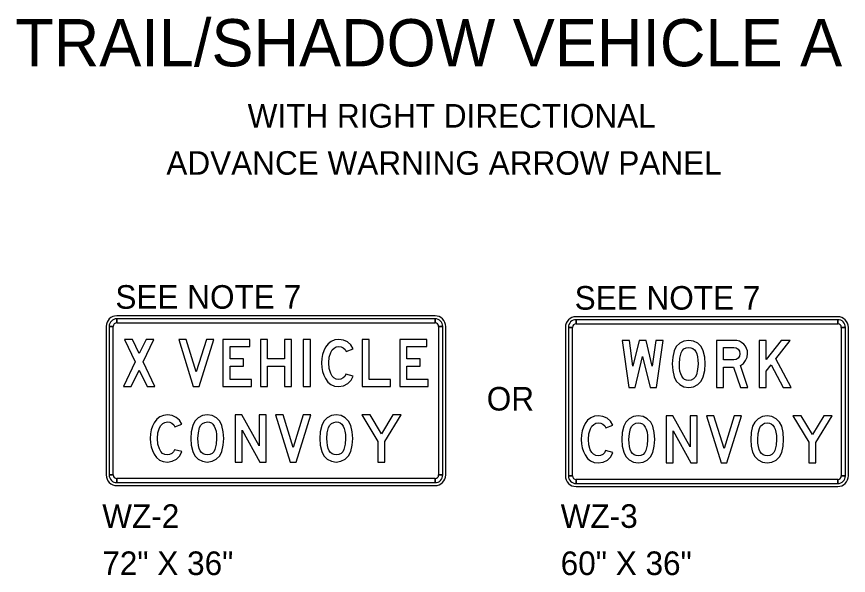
# Model space of a CAD drawing. Extents: x 1806907 to 1812607, y 675071 to 676228.
# Drawn here: x 1811769.5 to 1811981.1, y 675736.2 to 675878.3 of the extents above; entities that cross this region are included whole.
import ezdxf

# ---------------------------------------------------------------- set-up
doc = ezdxf.new("R2010")
doc.units = 0
doc.layers.add('Working Level 1', color=7, linetype='Continuous')

msp = doc.modelspace()

# ---------------------------------------------------------------- linework, layer by layer
at = {"layer": 'Working Level 1'}
for p, q in [((1811875.95, 675802.2), (1811794.95, 675802.2)), ((1811794.95, 675800.4), (1811794.95, 675801.45)), ((1811875.95, 675801.45), (1811875.95, 675800.4)), ((1811978.42, 675801.97), (1811911.82, 675801.97)), ((1811911.82, 675800.17), (1811911.82, 675801.22)), ((1811978.42, 675801.22), (1811978.42, 675800.17)), ((1811792.25, 675799.5), (1811792.25, 675761.7)), ((1811793, 675799.5), (1811794.05, 675799.5)), ((1811876.85, 675799.5), (1811877.9, 675799.5)), ((1811878.65, 675761.7), (1811878.65, 675799.5)), ((1811909.12, 675799.27), (1811909.12, 675761.47)), ((1811909.87, 675799.27), (1811910.92, 675799.27)), ((1811979.32, 675799.27), (1811980.37, 675799.27)), ((1811981.12, 675761.47), (1811981.12, 675799.27)), ((1811794.05, 675761.7), (1811793, 675761.7)), ((1811794.95, 675759.75), (1811794.95, 675760.8)), ((1811875.95, 675760.8), (1811875.95, 675759.75)), ((1811877.9, 675761.7), (1811876.85, 675761.7)), ((1811910.92, 675761.47), (1811909.87, 675761.47)), ((1811911.82, 675759.52), (1811911.82, 675760.57)), ((1811978.42, 675760.57), (1811978.42, 675759.52)), ((1811980.37, 675761.47), (1811979.32, 675761.47)), ((1811794.95, 675759), (1811875.95, 675759)), ((1811911.82, 675758.77), (1811978.42, 675758.77))]:
    msp.add_line(p, q, dxfattribs=at)
for points in [[(1811875.95, 675801.45), (1811794.95, 675801.45), (1811794.95, 675800.4), (1811875.95, 675800.4), (1811875.95, 675801.45)], [(1811978.42, 675801.22), (1811911.82, 675801.22), (1811911.82, 675800.17), (1811978.42, 675800.17), (1811978.42, 675801.22)], [(1811793, 675799.5), (1811793, 675761.7), (1811794.05, 675761.7), (1811794.05, 675799.5), (1811793, 675799.5)], [(1811877.9, 675761.7), (1811877.9, 675799.5), (1811876.85, 675799.5), (1811876.85, 675761.7), (1811877.9, 675761.7)], [(1811909.87, 675799.27), (1811909.87, 675761.47), (1811910.92, 675761.47), (1811910.92, 675799.27), (1811909.87, 675799.27)], [(1811980.37, 675761.47), (1811980.37, 675799.27), (1811979.32, 675799.27), (1811979.32, 675761.47), (1811980.37, 675761.47)], [(1811804.65, 675784.2), (1811801.66, 675790.48), (1811804.4, 675796.2), (1811802.39, 675796.2), (1811800.65, 675792.58), (1811798.93, 675796.2), (1811796.92, 675796.2), (1811799.65, 675790.47), (1811796.64, 675784.2), (1811798.64, 675784.2), (1811800.65, 675788.37), (1811802.64, 675784.2)], [(1811819.64, 675796.2), (1811817.74, 675796.2), (1811815.16, 675787.91), (1811812.59, 675796.2), (1811810.7, 675796.2), (1811814.42, 675784.2), (1811815.91, 675784.2)], [(1811829.2, 675786.01), (1811823.76, 675786.01), (1811823.76, 675789.41), (1811827.16, 675789.41), (1811827.16, 675791.22), (1811823.76, 675791.22), (1811823.76, 675794.39), (1811828.84, 675794.39), (1811828.84, 675796.2), (1811821.95, 675796.2), (1811821.95, 675784.2), (1811829.2, 675784.2)], [(1811839.43, 675784.2), (1811839.43, 675796.2), (1811837.62, 675796.2), (1811837.62, 675791.22), (1811833.32, 675791.22), (1811833.32, 675796.2), (1811831.51, 675796.2), (1811831.51, 675784.2), (1811833.32, 675784.2), (1811833.32, 675789.41), (1811837.62, 675789.41), (1811837.62, 675784.2)], [(1811844.2, 675784.2), (1811844.2, 675796.2), (1811842.39, 675796.2), (1811842.39, 675784.2)], [(1811855.08, 675786.86), (1811853.27, 675787.32), (1811853, 675786.8), (1811852.56, 675786.38), (1811852, 675786.1), (1811851.37, 675786.01), (1811850.74, 675786.11), (1811850.2, 675786.39), (1811849.75, 675786.87), (1811849.38, 675787.54), (1811849.01, 675788.77), (1811848.89, 675790.2), (1811849.01, 675791.64), (1811849.39, 675792.87), (1811849.77, 675793.53), (1811850.24, 675794.01), (1811850.79, 675794.29), (1811851.43, 675794.39), (1811852.03, 675794.3), (1811852.58, 675794.06), (1811853.03, 675793.66), (1811853.34, 675793.16), (1811855.08, 675793.84), (1811854.5, 675794.81), (1811853.64, 675795.56), (1811852.6, 675796.04), (1811851.46, 675796.2), (1811850.4, 675796.07), (1811849.48, 675795.7), (1811848.7, 675795.07), (1811848.04, 675794.2), (1811847.62, 675793.33), (1811847.32, 675792.38), (1811847.14, 675791.34), (1811847.08, 675790.21), (1811847.13, 675789.08), (1811847.31, 675788.04), (1811847.61, 675787.09), (1811848.03, 675786.22), (1811848.67, 675785.34), (1811849.45, 675784.71), (1811850.36, 675784.32), (1811851.4, 675784.2), (1811852.62, 675784.38), (1811853.72, 675784.94), (1811854.57, 675785.79)], [(1811864.64, 675784.2), (1811864.64, 675786.01), (1811859.2, 675786.01), (1811859.2, 675796.2), (1811857.39, 675796.2), (1811857.39, 675784.2)], [(1811874.21, 675786.01), (1811868.76, 675786.01), (1811868.76, 675789.41), (1811872.16, 675789.41), (1811872.16, 675791.22), (1811868.76, 675791.22), (1811868.76, 675794.39), (1811873.84, 675794.39), (1811873.84, 675796.2), (1811866.95, 675796.2), (1811866.95, 675784.2), (1811874.21, 675784.2)], [(1811933.98, 675795.96), (1811932.15, 675795.96), (1811931.23, 675789.39), (1811929.64, 675795.96), (1811927.89, 675795.96), (1811926.31, 675789.38), (1811925.39, 675795.96), (1811923.56, 675795.96), (1811925.24, 675783.97), (1811926.87, 675783.97), (1811928.77, 675791.86), (1811930.67, 675783.97), (1811932.3, 675783.97)], [(1811944.68, 675789.97), (1811944.56, 675791.68), (1811944.19, 675793.29), (1811943.65, 675794.37), (1811942.79, 675795.23), (1811941.71, 675795.78), (1811940.49, 675795.96), (1811939.27, 675795.78), (1811938.19, 675795.23), (1811937.33, 675794.37), (1811936.79, 675793.28), (1811936.43, 675791.67), (1811936.31, 675789.97), (1811936.43, 675788.27), (1811936.79, 675786.66), (1811937.33, 675785.58), (1811938.19, 675784.72), (1811939.27, 675784.15), (1811940.49, 675783.97), (1811941.7, 675784.15), (1811942.79, 675784.71), (1811943.64, 675785.56), (1811944.18, 675786.64), (1811944.55, 675788.25)], [(1811955.56, 675783.97), (1811953.67, 675789.57), (1811954.41, 675790.09), (1811954.98, 675790.81), (1811955.36, 675791.67), (1811955.48, 675792.59), (1811955.42, 675793.26), (1811955.23, 675793.88), (1811954.92, 675794.45), (1811954.48, 675794.97), (1811953.95, 675795.41), (1811953.38, 675795.72), (1811952.76, 675795.9), (1811952.08, 675795.96), (1811947.55, 675795.96), (1811947.55, 675783.97), (1811949.37, 675783.97), (1811949.37, 675789.17), (1811951.88, 675789.17), (1811953.65, 675783.97)], [(1811966.56, 675783.97), (1811962.66, 675791.28), (1811966.27, 675795.96), (1811963.98, 675795.96), (1811960.24, 675791.1), (1811960.24, 675795.96), (1811958.43, 675795.96), (1811958.43, 675783.97), (1811960.24, 675783.97), (1811960.24, 675788.14), (1811961.45, 675789.7), (1811964.51, 675783.97)], [(1811942.87, 675789.97), (1811942.76, 675788.51), (1811942.45, 675787.15), (1811942.16, 675786.59), (1811941.71, 675786.15), (1811941.14, 675785.87), (1811940.5, 675785.78), (1811939.94, 675785.84), (1811939.45, 675786.04), (1811939.04, 675786.36), (1811938.71, 675786.82), (1811938.45, 675787.41), (1811938.26, 675788.13), (1811938.15, 675788.98), (1811938.12, 675789.97), (1811938.22, 675791.42), (1811938.54, 675792.77), (1811938.83, 675793.33), (1811939.28, 675793.78), (1811939.85, 675794.06), (1811940.5, 675794.15), (1811941.05, 675794.09), (1811941.53, 675793.89), (1811941.94, 675793.56), (1811942.28, 675793.11), (1811942.53, 675792.52), (1811942.72, 675791.8), (1811942.83, 675790.95)], [(1811949.37, 675790.98), (1811949.37, 675794.15), (1811952.01, 675794.15), (1811952.58, 675794.03), (1811953.07, 675793.68), (1811953.4, 675793.17), (1811953.51, 675792.57), (1811953.4, 675791.96), (1811953.07, 675791.45), (1811952.58, 675791.1), (1811952.01, 675790.98)], [(1811811.49, 675767.66), (1811809.67, 675768.12), (1811809.41, 675767.6), (1811808.97, 675767.18), (1811808.4, 675766.9), (1811807.78, 675766.81), (1811807.15, 675766.91), (1811806.61, 675767.19), (1811806.15, 675767.67), (1811805.78, 675768.34), (1811805.41, 675769.57), (1811805.29, 675771), (1811805.42, 675772.44), (1811805.8, 675773.67), (1811806.18, 675774.33), (1811806.64, 675774.81), (1811807.2, 675775.09), (1811807.84, 675775.19), (1811808.44, 675775.1), (1811808.99, 675774.86), (1811809.44, 675774.46), (1811809.75, 675773.96), (1811811.49, 675774.64), (1811810.9, 675775.61), (1811810.05, 675776.36), (1811809.01, 675776.84), (1811807.87, 675777), (1811806.81, 675776.87), (1811805.89, 675776.5), (1811805.1, 675775.87), (1811804.45, 675775), (1811804.02, 675774.13), (1811803.72, 675773.18), (1811803.54, 675772.14), (1811803.48, 675771.01), (1811803.54, 675769.88), (1811803.72, 675768.84), (1811804.01, 675767.89), (1811804.44, 675767.02), (1811805.08, 675766.14), (1811805.85, 675765.51), (1811806.76, 675765.12), (1811807.81, 675765), (1811809.03, 675765.18), (1811810.12, 675765.74), (1811810.98, 675766.59)], [(1811822.17, 675771.01), (1811822.05, 675772.72), (1811821.68, 675774.32), (1811821.14, 675775.4), (1811820.28, 675776.26), (1811819.19, 675776.81), (1811817.97, 675777), (1811816.75, 675776.81), (1811815.67, 675776.26), (1811814.82, 675775.4), (1811814.28, 675774.31), (1811813.91, 675772.71), (1811813.79, 675771.01), (1811813.91, 675769.31), (1811814.28, 675767.7), (1811814.82, 675766.61), (1811815.67, 675765.75), (1811816.75, 675765.19), (1811817.97, 675765), (1811819.19, 675765.18), (1811820.27, 675765.74), (1811821.13, 675766.59), (1811821.67, 675767.68), (1811822.04, 675769.29)], [(1811832.97, 675765), (1811832.97, 675777), (1811831.16, 675777), (1811831.16, 675769.11), (1811826.78, 675777), (1811825.04, 675777), (1811825.04, 675765), (1811826.86, 675765), (1811826.86, 675773.14), (1811831.37, 675765)], [(1811844.29, 675777), (1811842.4, 675777), (1811839.82, 675768.71), (1811837.25, 675777), (1811835.36, 675777), (1811839.07, 675765), (1811840.56, 675765)], [(1811854.98, 675771.01), (1811854.86, 675772.72), (1811854.49, 675774.32), (1811853.95, 675775.4), (1811853.09, 675776.26), (1811852.01, 675776.81), (1811850.79, 675777), (1811849.57, 675776.81), (1811848.49, 675776.26), (1811847.63, 675775.4), (1811847.09, 675774.31), (1811846.73, 675772.71), (1811846.61, 675771.01), (1811846.73, 675769.31), (1811847.09, 675767.7), (1811847.63, 675766.61), (1811848.49, 675765.75), (1811849.57, 675765.19), (1811850.79, 675765), (1811852, 675765.18), (1811853.09, 675765.74), (1811853.94, 675766.59), (1811854.48, 675767.68), (1811854.85, 675769.29)], [(1811867.35, 675777), (1811865.22, 675777), (1811862.28, 675772.21), (1811859.4, 675777), (1811857.29, 675777), (1811861.37, 675770.26), (1811861.37, 675765), (1811863.18, 675765), (1811863.18, 675770.21)], [(1811921.16, 675767.43), (1811919.34, 675767.89), (1811919.07, 675767.36), (1811918.64, 675766.95), (1811918.07, 675766.67), (1811917.45, 675766.58), (1811916.82, 675766.67), (1811916.28, 675766.96), (1811915.82, 675767.44), (1811915.45, 675768.11), (1811915.08, 675769.34), (1811914.96, 675770.77), (1811915.08, 675772.2), (1811915.47, 675773.44), (1811915.84, 675774.1), (1811916.31, 675774.57), (1811916.86, 675774.86), (1811917.51, 675774.96), (1811918.11, 675774.87), (1811918.65, 675774.62), (1811919.11, 675774.23), (1811919.42, 675773.73), (1811921.16, 675774.41), (1811920.57, 675775.37), (1811919.71, 675776.12), (1811918.67, 675776.6), (1811917.54, 675776.77), (1811916.48, 675776.64), (1811915.56, 675776.26), (1811914.77, 675775.64), (1811914.11, 675774.76), (1811913.69, 675773.9), (1811913.39, 675772.95), (1811913.21, 675771.9), (1811913.15, 675770.77), (1811913.21, 675769.65), (1811913.39, 675768.61), (1811913.68, 675767.65), (1811914.1, 675766.79), (1811914.74, 675765.9), (1811915.52, 675765.27), (1811916.43, 675764.89), (1811917.48, 675764.77), (1811918.7, 675764.95), (1811919.79, 675765.51), (1811920.65, 675766.36)], [(1811931.84, 675770.77), (1811931.71, 675772.49), (1811931.35, 675774.09), (1811930.81, 675775.17), (1811929.95, 675776.03), (1811928.86, 675776.58), (1811927.64, 675776.77), (1811926.42, 675776.58), (1811925.34, 675776.03), (1811924.49, 675775.17), (1811923.95, 675774.08), (1811923.58, 675772.48), (1811923.46, 675770.77), (1811923.58, 675769.07), (1811923.95, 675767.47), (1811924.49, 675766.38), (1811925.34, 675765.52), (1811926.42, 675764.95), (1811927.64, 675764.77), (1811928.86, 675764.95), (1811929.94, 675765.51), (1811930.8, 675766.36), (1811931.34, 675767.45), (1811931.71, 675769.05)], [(1811942.63, 675764.77), (1811942.63, 675776.77), (1811940.82, 675776.77), (1811940.82, 675768.88), (1811936.45, 675776.77), (1811934.71, 675776.77), (1811934.71, 675764.77), (1811936.52, 675764.77), (1811936.52, 675772.91), (1811941.04, 675764.77)], [(1811953.96, 675776.77), (1811952.06, 675776.77), (1811949.49, 675768.47), (1811946.92, 675776.77), (1811945.02, 675776.77), (1811948.74, 675764.77), (1811950.23, 675764.77)], [(1811964.65, 675770.77), (1811964.53, 675772.49), (1811964.16, 675774.09), (1811963.62, 675775.17), (1811962.76, 675776.03), (1811961.67, 675776.58), (1811960.45, 675776.77), (1811959.23, 675776.58), (1811958.15, 675776.03), (1811957.3, 675775.17), (1811956.76, 675774.08), (1811956.39, 675772.48), (1811956.27, 675770.77), (1811956.39, 675769.07), (1811956.76, 675767.47), (1811957.3, 675766.38), (1811958.15, 675765.52), (1811959.23, 675764.95), (1811960.45, 675764.77), (1811961.67, 675764.95), (1811962.75, 675765.51), (1811963.61, 675766.36), (1811964.15, 675767.45), (1811964.52, 675769.05)], [(1811977.02, 675776.77), (1811974.89, 675776.77), (1811971.95, 675771.98), (1811969.07, 675776.77), (1811966.96, 675776.77), (1811971.04, 675770.02), (1811971.04, 675764.77), (1811972.85, 675764.77), (1811972.85, 675769.97)], [(1811820.36, 675771), (1811820.25, 675769.54), (1811819.93, 675768.19), (1811819.64, 675767.62), (1811819.19, 675767.18), (1811818.63, 675766.9), (1811817.99, 675766.81), (1811817.43, 675766.87), (1811816.94, 675767.07), (1811816.53, 675767.4), (1811816.2, 675767.86), (1811815.94, 675768.45), (1811815.75, 675769.17), (1811815.64, 675770.02), (1811815.6, 675771), (1811815.71, 675772.45), (1811816.03, 675773.8), (1811816.31, 675774.37), (1811816.76, 675774.81), (1811817.33, 675775.09), (1811817.99, 675775.19), (1811818.54, 675775.12), (1811819.02, 675774.93), (1811819.43, 675774.6), (1811819.76, 675774.14), (1811820.02, 675773.55), (1811820.21, 675772.83), (1811820.32, 675771.98)], [(1811853.17, 675771), (1811853.06, 675769.54), (1811852.75, 675768.19), (1811852.46, 675767.62), (1811852.01, 675767.18), (1811851.44, 675766.9), (1811850.8, 675766.81), (1811850.24, 675766.87), (1811849.75, 675767.07), (1811849.34, 675767.4), (1811849.01, 675767.86), (1811848.75, 675768.45), (1811848.56, 675769.17), (1811848.45, 675770.02), (1811848.42, 675771), (1811848.52, 675772.45), (1811848.84, 675773.8), (1811849.13, 675774.37), (1811849.58, 675774.81), (1811850.15, 675775.09), (1811850.8, 675775.19), (1811851.35, 675775.12), (1811851.83, 675774.93), (1811852.24, 675774.6), (1811852.58, 675774.14), (1811852.83, 675773.55), (1811853.02, 675772.83), (1811853.13, 675771.98)], [(1811930.03, 675770.77), (1811929.92, 675769.31), (1811929.6, 675767.95), (1811929.31, 675767.39), (1811928.86, 675766.95), (1811928.3, 675766.67), (1811927.66, 675766.58), (1811927.09, 675766.64), (1811926.61, 675766.84), (1811926.2, 675767.17), (1811925.87, 675767.63), (1811925.61, 675768.21), (1811925.42, 675768.93), (1811925.31, 675769.78), (1811925.27, 675770.77), (1811925.38, 675772.22), (1811925.7, 675773.57), (1811925.98, 675774.13), (1811926.43, 675774.58), (1811927, 675774.86), (1811927.66, 675774.96), (1811928.21, 675774.89), (1811928.69, 675774.69), (1811929.1, 675774.36), (1811929.43, 675773.91), (1811929.69, 675773.32), (1811929.88, 675772.6), (1811929.99, 675771.75)], [(1811962.84, 675770.77), (1811962.73, 675769.31), (1811962.41, 675767.95), (1811962.12, 675767.39), (1811961.67, 675766.95), (1811961.11, 675766.67), (1811960.47, 675766.58), (1811959.91, 675766.64), (1811959.42, 675766.84), (1811959.01, 675767.17), (1811958.68, 675767.63), (1811958.42, 675768.21), (1811958.23, 675768.93), (1811958.12, 675769.78), (1811958.08, 675770.77), (1811958.19, 675772.22), (1811958.51, 675773.57), (1811958.79, 675774.13), (1811959.24, 675774.58), (1811959.81, 675774.86), (1811960.47, 675774.96), (1811961.02, 675774.89), (1811961.5, 675774.69), (1811961.91, 675774.36), (1811962.24, 675773.91), (1811962.5, 675773.32), (1811962.69, 675772.6), (1811962.8, 675771.75)], [(1811794.95, 675759.75), (1811875.95, 675759.75), (1811875.95, 675760.8), (1811794.95, 675760.8), (1811794.95, 675759.75)], [(1811911.82, 675759.52), (1811978.42, 675759.52), (1811978.42, 675760.57), (1811911.82, 675760.57), (1811911.82, 675759.52)]]:
    msp.add_lwpolyline(points, close=True, dxfattribs=at)
for centre, radius, start, end in [((1811794.95, 675799.5), 2.7, 90.0002, 179.9998), ((1811794.95, 675799.5), 1.95, 90.0002, 179.9998), ((1811875.95, 675799.5), 2.7, 0, 90.0002), ((1811875.95, 675799.5), 1.95, 0, 90.0002), ((1811911.82, 675799.27), 2.7, 90.0002, 179.9998), ((1811911.82, 675799.27), 1.95, 90.0002, 179.9998), ((1811978.42, 675799.27), 2.7, 0, 90.0002), ((1811978.42, 675799.27), 1.95, 0, 90.0002), ((1811794.95, 675799.5), 0.9, 90.0002, 179.9998), ((1811875.95, 675799.5), 0.9, 0, 90.0002), ((1811911.82, 675799.27), 0.9, 90.0002, 179.9998), ((1811978.42, 675799.27), 0.9, 0, 90.0002), ((1811794.95, 675761.7), 2.7, 179.9998, 270.0001), ((1811794.95, 675761.7), 1.95, 179.9998, 270.0001), ((1811794.95, 675761.7), 0.9, 179.9998, 270.0001), ((1811875.95, 675761.7), 2.7, 270.0001, 0.0003), ((1811875.95, 675761.7), 1.95, 270.0001, 0.0003), ((1811875.95, 675761.7), 0.9, 270.0001, 0.0003), ((1811911.82, 675761.47), 2.7, 179.9998, 270.0001), ((1811911.82, 675761.47), 1.95, 179.9998, 270.0001), ((1811911.82, 675761.47), 0.9, 179.9998, 270.0001), ((1811978.42, 675761.47), 2.7, 270.0001, 0.0003), ((1811978.42, 675761.47), 1.95, 270.0001, 0.0003), ((1811978.42, 675761.47), 0.9, 270.0001, 0.0003)]:
    msp.add_arc(centre, radius, start, end, dxfattribs=at)

# ---------------------------------------------------------------- texts
for s, height, p in [('TRAIL/SHADOW VEHICLE A', 12, (1811769.1, 675865.7)), ('WITH RIGHT DIRECTIONAL', 6, (1811828.25, 675850.1)), ('ADVANCE WARNING ARROW PANEL', 6, (1811807.56, 675838.1)), ('SEE NOTE 7 ', 6, (1811794.59, 675804.01)), ('SEE NOTE 7 ', 6, (1811911.46, 675803.77))]:
    msp.add_text(s, height=height, dxfattribs=at).set_placement(p)
for s, p in [('OR', (1811889.09, 675778.1)), ('WZ-2', (1811791.25, 675748.24)), ('WZ-3', (1811907.91, 675748.24)), ('72" X 36"', (1811791.25, 675736.24)), ('60" X 36"', (1811907.91, 675736.24))]:
    msp.add_text(s, height=6, rotation=0, dxfattribs=at).set_placement(p)

doc.saveas('drawing.dxf')
